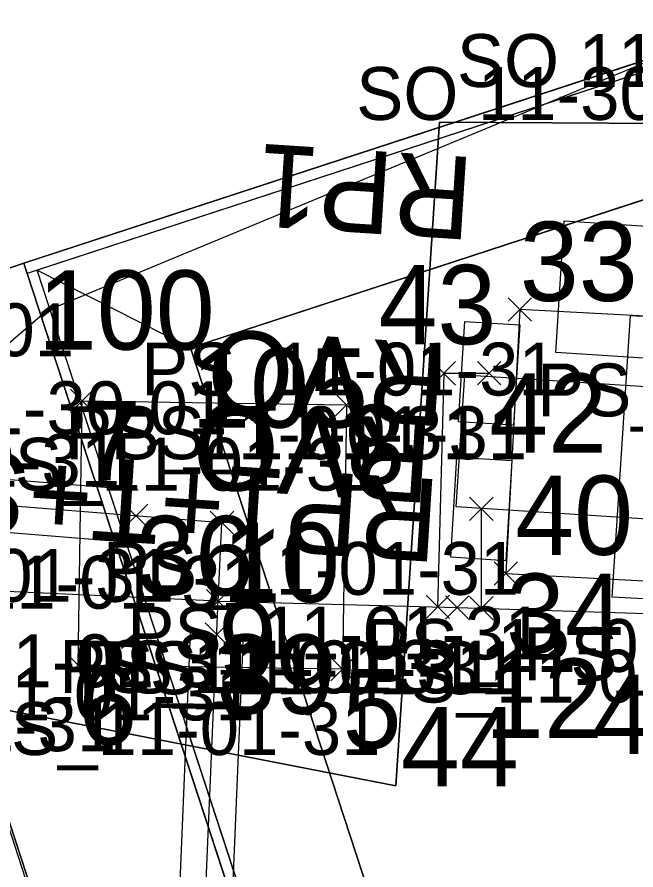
# Model space of a CAD drawing. Extents: x -728800 to -728100, y -1073200 to -1072700.
# Drawn here: x -728496.71 to -728492.02, y -1073040.01 to -1073033.55 of the extents above; entities that cross this region are included whole.
import ezdxf

# ---------------------------------------------------------------- set-up
doc = ezdxf.new("R2010")
doc.units = 0
for name, color, linetype in [('_NOR-návrh tenká', 7, 'Continuous'), ('_NOR-VDZ', 7, 'Continuous'), ('_NOR-šraf_+-0', 7, 'Continuous'), ('_NOR-šraf_+12', 7, 'Continuous'), ('_NOR-šraf_+6', 7, 'Continuous'), ('_NOR-šraf_chodník', 7, 'Continuous'), ('_NOR-šraf_vozovka', 7, 'Continuous'), ('_NOR-šraf_zeleň', 7, 'Continuous'), ('B1_body_poloha', 7, 'Continuous'), ('B2_body_číslo', 7, 'Continuous'), ('B3_body_popiska', 7, 'Continuous'), ('B6_JŽM', 7, 'Continuous'), ('KOS_kabelová trasa', 7, 'Continuous'), ('KOS_nové prvky PZZ', 7, 'Continuous'), ('KTA_PZZ rušené', 7, 'Continuous'), ('ZA_01_Trvalý_pro_SŽDC_dle_UMVZST', 7, 'Continuous'), ('ZA_02_Dočasný_do_1_roku', 7, 'Continuous')]:
    doc.layers.add(name, color=color, linetype=linetype)

msp = doc.modelspace()

# ---------------------------------------------------------------- linework, layer by layer
at = {"layer": '_NOR-návrh tenká'}
for p, q in [((-728496.6299, -1073035.4928), (-728496.6548, -1073035.4168)), ((-728494.83, -1073040.995), (-728496.6299, -1073035.4928)), ((-728494.7442, -1073041.0001), (-728496.5539, -1073035.4679)), ((-728495.8946, -1073042.3079), (-728497.9796, -1073035.9343)), ((-728496.2444, -1073041.2869), (-728497.97, -1073036.0119)), ((-728493.7572, -1073041.0582), (-728495.3935, -1073036.0563))]:
    msp.add_line(p, q, dxfattribs=at)
for points in [[(-728488.1062, -1073032.7044), (-728496.6299, -1073035.4928)], [(-728489.0615, -1073032.9328), (-728496.6548, -1073035.4168)], [(-728487.8202, -1073033.5788), (-728495.3935, -1073036.0563)]]:
    msp.add_lwpolyline(points, dxfattribs=at)
for radius, end in [(12.3, 176.17795), (12, 176.26453), (11.85, 176.30947)]:
    msp.add_arc((-728489.7733, -1073039.2055), radius, 105.42005, end, dxfattribs=at)
at = {"layer": '_NOR-VDZ'}
msp.add_arc((-728489.7733, -1073039.2055), 12.15, 116.96186, 176.2207, dxfattribs=at)
at = {"layer": '_NOR-šraf_+-0'}
msp.add_lwpolyline([(-728494.83, -1073040.995), (-728494.7442, -1073041.0001), (-728496.5539, -1073035.4679), (-728496.6299, -1073035.4928), (-728494.83, -1073040.995), (-728494.83, -1073040.995)], dxfattribs=at)
at = {"layer": '_NOR-šraf_+12'}
for radius, end in [(12, 176.26453), (11.85, 176.30947)]:
    msp.add_arc((-728489.7733, -1073039.2055), radius, 121.87344, end, dxfattribs=at)
at = {"layer": '_NOR-šraf_+6'}
msp.add_line((-728496.7975, -1073039.5476), (-728496.5255, -1073040.3793), dxfattribs=at)
msp.add_lwpolyline([(-728496.6548, -1073035.4168), (-728491.3522, -1073033.6821), (-728490.5897, -1073033.4327), (-728489.0615, -1073032.9328), (-728488.9853, -1073032.9078), (-728488.6063, -1073032.7839), (-728488.5939, -1073032.8219), (-728488.5814, -1073032.8599), (-728496.5539, -1073035.4679), (-728496.6299, -1073035.4928), (-728496.6548, -1073035.4168), (-728496.6548, -1073035.4168)], dxfattribs=at)
at = {"layer": '_NOR-šraf_chodník'}
for p, q in [((-728491.3522, -1073033.6821), (-728496.6548, -1073035.4168)), ((-728498.0044, -1073035.8583), (-728496.6548, -1073035.4168)), ((-728496.6548, -1073035.4168), (-728497.6504, -1073035.7425)), ((-728496.6548, -1073035.4168), (-728496.6472, -1073035.44)), ((-728496.6472, -1073035.44), (-728494.83, -1073040.995)), ((-728495.8946, -1073042.3079), (-728497.9906, -1073035.9006))]:
    msp.add_line(p, q, dxfattribs=at)
at = {"layer": '_NOR-šraf_vozovka'}
for radius, start, end in [(12.3, 105.42005, 176.17795), (12, 121.87344, 176.26453)]:
    msp.add_arc((-728489.7733, -1073039.2055), radius, start, end, dxfattribs=at)
at = {"layer": '_NOR-šraf_zeleň'}
for p, q in [((-728488.1062, -1073032.7044), (-728496.5539, -1073035.4679)), ((-728495.3935, -1073036.0563), (-728487.8202, -1073033.5788)), ((-728496.5539, -1073035.4679), (-728495.3935, -1073036.0563)), ((-728494.7442, -1073041.0001), (-728496.5539, -1073035.4679)), ((-728496.5539, -1073035.4679), (-728495.3935, -1073036.0563)), ((-728495.3935, -1073036.0563), (-728493.7572, -1073041.0582))]:
    msp.add_line(p, q, dxfattribs=at)
msp.add_arc((-728489.7733, -1073039.2055), 11.85, 121.87344, 157.33044, dxfattribs=at)
at = {"layer": 'B1_body_poloha'}
for p, q in [((-728492.9914, -1073035.6786), (-728492.8146, -1073035.8554)), ((-728492.9914, -1073035.8554), (-728492.8146, -1073035.6786)), ((-728493.5667, -1073036.161), (-728493.3899, -1073036.3378)), ((-728493.5667, -1073036.3378), (-728493.3899, -1073036.161)), ((-728493.2234, -1073036.1606), (-728493.0466, -1073036.3374)), ((-728493.2234, -1073036.3374), (-728493.0466, -1073036.1606)), ((-728496.3034, -1073036.3696), (-728496.1266, -1073036.5464)), ((-728496.3034, -1073036.5464), (-728496.1266, -1073036.3696)), ((-728494.3034, -1073036.3986), (-728494.1266, -1073036.5754)), ((-728494.3034, -1073036.5754), (-728494.1266, -1073036.3986)), ((-728493.2824, -1073037.1866), (-728493.1056, -1073037.3634)), ((-728493.2824, -1073037.3634), (-728493.1056, -1073037.1866)), ((-728495.8954, -1073037.2396), (-728495.7186, -1073037.4164)), ((-728495.8954, -1073037.4164), (-728495.7186, -1073037.2396)), ((-728495.2448, -1073037.2914), (-728495.068, -1073037.4682)), ((-728495.2448, -1073037.4682), (-728495.068, -1073037.2914)), ((-728493.0964, -1073037.6756), (-728492.9196, -1073037.8524)), ((-728493.0964, -1073037.8524), (-728492.9196, -1073037.6756)), ((-728495.2734, -1073037.8856), (-728495.0966, -1073038.0624)), ((-728495.2734, -1073038.0624), (-728495.0966, -1073037.8856)), ((-728493.6124, -1073037.9286), (-728493.4356, -1073038.1054)), ((-728493.6124, -1073038.1054), (-728493.4356, -1073037.9286)), ((-728493.4654, -1073037.9326), (-728493.2886, -1073038.1094)), ((-728493.4654, -1073038.1094), (-728493.2886, -1073037.9326)), ((-728493.2824, -1073037.9386), (-728493.1056, -1073038.1154)), ((-728493.2824, -1073038.1154), (-728493.1056, -1073037.9386)), ((-728495.2844, -1073038.1366), (-728495.1076, -1073038.3134)), ((-728495.2844, -1073038.3134), (-728495.1076, -1073038.1366)), ((-728496.3324, -1073038.3696), (-728496.1556, -1073038.5464)), ((-728496.3324, -1073038.5464), (-728496.1556, -1073038.3696)), ((-728494.3324, -1073038.3986), (-728494.1556, -1073038.5754)), ((-728494.3324, -1073038.5754), (-728494.1556, -1073038.3986))]:
    msp.add_line(p, q, dxfattribs=at)
at = {"layer": 'B2_body_číslo'}
for p, q in [((-728496.55, -1073035.47), (-728496.55, -1073035.47)), ((-728492.903, -1073035.767), (-728492.903, -1073035.767)), ((-728495.39, -1073036.06), (-728495.39, -1073036.06)), ((-728493.478, -1073036.249), (-728493.478, -1073036.249)), ((-728493.135, -1073036.249), (-728493.135, -1073036.249)), ((-728496.215, -1073036.458), (-728496.215, -1073036.458)), ((-728494.215, -1073036.487), (-728494.215, -1073036.487)), ((-728495.807, -1073037.328), (-728495.807, -1073037.328)), ((-728493.194, -1073037.275), (-728493.194, -1073037.275)), ((-728495.156, -1073037.38), (-728495.156, -1073037.38)), ((-728493.008, -1073037.764), (-728493.008, -1073037.764)), ((-728495.185, -1073037.974), (-728495.185, -1073037.974)), ((-728493.524, -1073038.017), (-728493.524, -1073038.017)), ((-728493.377, -1073038.021), (-728493.377, -1073038.021)), ((-728493.194, -1073038.027), (-728493.194, -1073038.027)), ((-728495.196, -1073038.225), (-728495.196, -1073038.225)), ((-728496.244, -1073038.458), (-728496.244, -1073038.458)), ((-728494.244, -1073038.487), (-728494.244, -1073038.487))]:
    msp.add_line(p, q, dxfattribs=at)
at = {"layer": 'B6_JŽM'}
for points in [[(-728449.745, -1073020.446), (-728480.35, -1073030.208), (-728490.255, -1073033.191), (-728496.482, -1073035.776)], [(-728496.482, -1073035.776), (-728497.4937, -1073036.6437), (-728498.316, -1073037.996), (-728498.5283, -1073038.6029), (-728498.459, -1073039.486), (-728498.149, -1073040.1285), (-728497.5331, -1073040.6035), (-728496.825, -1073040.892), (-728494.827, -1073041.079), (-728486.835, -1073041.479), (-728486.937, -1073042.858), (-728494.923, -1073042.391), (-728498.977, -1073042.014), (-728499.069, -1073042.727), (-728513.553, -1073040.642)]]:
    msp.add_lwpolyline(points, dxfattribs=at)
at = {"layer": 'KOS_kabelová trasa'}
for p, q in [((-728495.7911, -1073037.1327), (-728513.1719, -1073035.7399)), ((-728495.823, -1073037.5314), (-728513.2038, -1073036.1386)), ((-728495.7665, -1073047.15), (-728495.3938, -1073038.2172)), ((-728495.3669, -1073047.1667), (-728494.9941, -1073038.2339))]:
    msp.add_line(p, q, dxfattribs=at)
for points in [[(-728495.1847, -1073037.9739), (-728495.1564, -1073037.3798), (-728513.9156, -1073035.8794)], [(-728493.135, -1073036.2494), (-728493.4783, -1073036.2494), (-728493.5244, -1073038.0172)], [(-728493.194, -1073037.2747), (-728493.194, -1073038.0269)], [(-728495.1847, -1073037.9739), (-728493.3766, -1073038.021), (-728491.2286, -1073038.0902), (-728491.2101, -1073037.5146)], [(-728495.1847, -1073037.9739), (-728498.6645, -1073037.8132)], [(-728499.6877, -1073048.4364), (-728495.6152, -1073048.0137), (-728495.1842, -1073037.964)]]:
    msp.add_lwpolyline(points, dxfattribs=at)
msp.add_lwpolyline([(-728494.2441, -1073038.4872), (-728496.2439, -1073038.4579), (-728496.2146, -1073036.4581), (-728494.2148, -1073036.4874)], close=True, dxfattribs=at)
at = {"layer": 'KOS_nové prvky PZZ'}
for points in [[(-728489.907, -1073035.925), (-728492.9028, -1073035.7668), (-728493.0083, -1073037.764), (-728490.0125, -1073037.9222)], [(-728493.32, -1073035.8573), (-728492.9037, -1073035.8827), (-728492.95, -1073036.6416), (-728493.3663, -1073036.6162)], [(-728493.379, -1073036.8825), (-728492.9627, -1073036.9079), (-728493.0091, -1073037.6668), (-728493.4253, -1073037.6414)]]:
    msp.add_lwpolyline(points, close=True, dxfattribs=at)
at = {"layer": 'KTA_PZZ rušené'}
for points in [[(-728490.571, -1073035.2232), (-728490.6351, -1073036.2211), (-728492.631, -1073036.0928), (-728492.5669, -1073035.0949), (-728490.571, -1073035.2232)], [(-728490.044, -1073038.056), (-728492.203, -1073037.942), (-728492.066, -1073035.811), (-728489.907, -1073035.925), (-728490.044, -1073038.056)], [(-728491.324, -1073036.3902), (-728491.3881, -1073037.3881), (-728493.384, -1073037.2598), (-728493.3199, -1073036.2619), (-728491.324, -1073036.3902)]]:
    msp.add_lwpolyline(points, dxfattribs=at)
at = {"layer": 'ZA_01_Trvalý_pro_SŽDC_dle_UMVZST'}
msp.add_lwpolyline([(-728500.7194, -1073036.1609), (-728501.19, -1073037.94), (-728493.84, -1073039.37), (-728493.51, -1073034.35), (-728488.39, -1073034.38), (-728491.3018, -1073027.3013), (-728493.68, -1073027.94), (-728497.54, -1073030.15), (-728499.78, -1073032.61)], close=True, dxfattribs=at)
at = {"layer": 'ZA_02_Dočasný_do_1_roku'}
msp.add_lwpolyline([(-728493.1267, -1073026.8514), (-728494.629, -1073027.3499), (-728496.2837, -1073028.1637), (-728498.4547, -1073029.8063), (-728499.6945, -1073031.1155), (-728500.7898, -1073032.7007), (-728501.6149, -1073034.32), (-728501.8023, -1073034.8884), (-728501.5592, -1073036.1001), (-728500.7194, -1073036.1609), (-728499.78, -1073032.61), (-728497.54, -1073030.15), (-728493.68, -1073027.94), (-728491.3018, -1073027.3013), (-728488.39, -1073034.38), (-728493.51, -1073034.35), (-728493.84, -1073039.37), (-728501.19, -1073037.94), (-728502.0422, -1073043.9717)], dxfattribs=at)

# ---------------------------------------------------------------- texts
at = {"layer": 'B2_body_číslo'}
for s, p in [('33', (-728492.903, -1073035.702)), ('43', (-728493.9728, -1073036.0288)), ('100', (-728496.55, -1073036.07)), ('105', (-728495.39, -1073036.66)), ('42', (-728493.135, -1073036.849)), ('7', (-728496.215, -1073037.058)), ('8', (-728494.215, -1073037.087)), ('40', (-728492.9382, -1073037.6226)), ('36', (-728495.807, -1073037.928)), ('10', (-728495.156, -1073037.98)), ('34', (-728493.008, -1073038.364)), ('9', (-728495.185, -1073038.574)), ('39', (-728495.196, -1073038.825)), ('12', (-728493.166, -1073039.0078)), ('6', (-728496.244, -1073039.058)), ('5', (-728494.244, -1073039.087)), ('41', (-728492.3507, -1073039.1302)), ('44', (-728493.8025, -1073039.3728))]:
    msp.add_text(s, height=0.6, dxfattribs=at).set_placement(p)
at = {"layer": 'B3_body_popiska'}
for s, p in [('SO 11-30-01', (-728493.3787, -1073034.083)), ('SO 11-30-01', (-728494.1407, -1073034.332)), ('SO 11-30-01', (-728499.3387, -1073036.12)), ('PS_11-01-31', (-728495.768, -1073036.417)), ('PS_11-01-31', (-728492.772, -1073036.575)), ('SO 11-30-01', (-728498.1787, -1073036.71)), ('PS_11-01-31', (-728496.343, -1073036.899)), ('PS_11-01-31', (-728496, -1073036.899)), ('PS_11-01-31', (-728499.08, -1073037.108)), ('PS_11-01-31', (-728497.08, -1073037.137)), ('PS_11-01-31', (-728496.059, -1073037.925)), ('PS_11-01-31', (-728498.672, -1073037.978)), ('PS_11-01-31', (-728498.021, -1073038.03)), ('PS_11-01-31', (-728495.873, -1073038.414)), ('PS_11-01-31', (-728494.086, -1073038.508)), ('PS_11-01-31', (-728492.877, -1073038.572)), ('PS_11-01-31', (-728498.05, -1073038.624)), ('PS_11-01-31', (-728496.389, -1073038.667)), ('PS_11-01-31', (-728496.242, -1073038.671)), ('PS_11-01-31', (-728496.059, -1073038.677)), ('PS_11-01-31', (-728494.094, -1073038.74)), ('PS_11-01-31', (-728498.061, -1073038.875)), ('PS_11-01-31', (-728499.109, -1073039.108)), ('PS_11-01-31', (-728497.109, -1073039.137))]:
    msp.add_text(s, height=0.4, dxfattribs=at).set_placement(p)
at = {"layer": 'KOS_nové prvky PZZ'}
for s, p in [('RVO', (-728493.4377, -1073036.0285)), ('RP1+T+SMO', (-728493.4967, -1073037.0538))]:
    msp.add_text(s, height=0.625, rotation=176.3219, dxfattribs=at).set_placement(p)
at = {"layer": 'KTA_PZZ rušené'}
for s, p in [('RP1', (-728493.2414, -1073034.616)), ('RVO', (-728493.5487, -1073036.6075))]:
    msp.add_text(s, height=0.625, rotation=176.3219, dxfattribs=at).set_placement(p)

doc.saveas('drawing.dxf')
